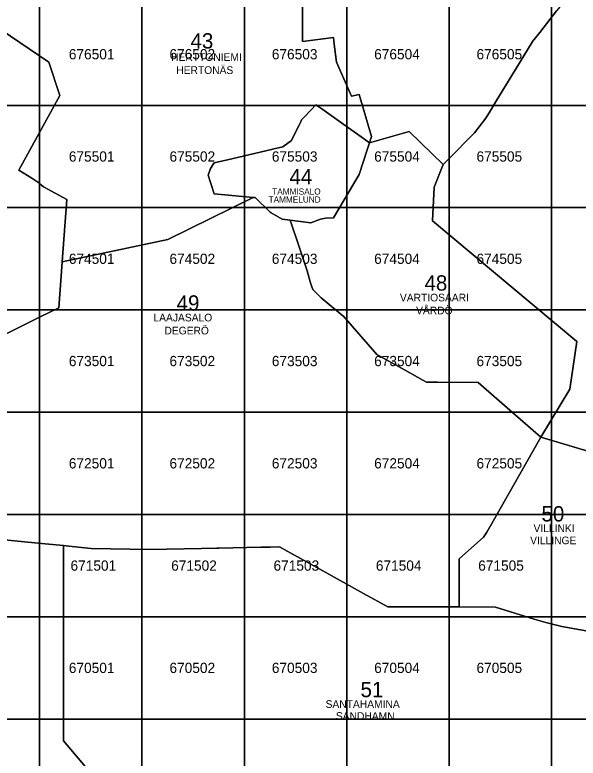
# Model space of a CAD drawing. Extents: x 25485000 to 25520000, y 6656775 to 6690000.
# Drawn here: x 25500758 to 25506262, y 6669617 to 6676885 of the extents above; entities that cross this region are included whole.
import ezdxf

# ---------------------------------------------------------------- set-up
doc = ezdxf.new("R2010")
doc.units = 0
doc.layers.add('Level 63', color=7, linetype='Continuous')

msp = doc.modelspace()

# ---------------------------------------------------------------- linework, layer by layer
at = {"layer": 'Level 63'}
for points in [[(25506321.3, 6677251.8), (25506203.7, 6677109.7), (25506049.4, 6676923.5), (25505887.3, 6676713.1), (25505815.7, 6676624.4), (25505811, 6676618.2), (25505576.6, 6676232), (25505550.7, 6676189.2), (25505535.7, 6676164.4), (25505465.4, 6676048), (25505444.7, 6676013.7), (25505402.6, 6675943.9), (25505360.4, 6675873.9), (25505248.6, 6675730.3), (25504991.1, 6675470.2), (25504941.6, 6675420.2), (25504854.1, 6675200.3), (25504837.4, 6674871.4), (25505612.3, 6674222.2), (25506247.7, 6673689.9), (25506181.2, 6673225), (25505895.6, 6672754.3), (25506849.3, 6672473)], [(25500427.3, 6676867.8), (25501089.3, 6676421.3), (25501195.8, 6676096.2), (25500795.1, 6675367.1), (25500923.2, 6675287.2), (25500990.4, 6675243.8), (25501002.9, 6675233.3), (25501038.4, 6675203.7), (25501266.2, 6675078.7), (25501221.4, 6674470.4), (25502253, 6674688.7), (25503087.4, 6675099.5), (25502704.3, 6675133.4), (25502675.4, 6675225.8), (25502669.1, 6675246), (25502647, 6675317.3), (25502668.1, 6675383.4), (25502704.6, 6675438.5), (25502834.9, 6675468.7), (25503264.5, 6675568.3), (25503274.3, 6675570.6), (25503376.8, 6675594.3), (25503462.2, 6675655.5), (25503527.3, 6675789.1), (25503538.6, 6675813.6), (25503547.9, 6675833.6), (25503560, 6675859.5), (25503593.1, 6675893.5), (25503640.2, 6675943.1), (25503649.2, 6675952.5), (25503698.8, 6676004.7), (25503757.2, 6675964.8), (25504165.1, 6675676.5), (25504222.9, 6675632.8), (25504242.8, 6675694.6), (25504121.7, 6676106.9), (25504046.4, 6676088.7), (25504020.2, 6676149), (25503902, 6676421.7), (25503879.2, 6676598.2), (25503872.4, 6676664.5), (25503567, 6676625), (25503567.2, 6677219.8)], [(25503567.2, 6677219.8), (25503567, 6676625), (25503872.4, 6676664.5), (25503879.2, 6676598.2), (25503902, 6676421.7), (25504020.2, 6676149), (25504046.4, 6676088.7), (25504121.7, 6676106.9), (25504242.8, 6675694.6), (25504222.9, 6675632.8), (25504609.9, 6675742.9), (25504941.6, 6675420.2), (25504991.1, 6675470.2), (25505248.6, 6675730.3), (25505360.4, 6675873.9), (25505402.6, 6675943.9), (25505444.7, 6676013.7), (25505465.4, 6676048), (25505535.7, 6676164.4), (25505550.7, 6676189.2), (25505576.6, 6676232), (25505811, 6676618.2), (25505815.7, 6676624.4), (25505887.3, 6676713.1), (25506049.4, 6676923.5)], [(25500113.5, 6673489.1), (25501011.9, 6673933.9), (25501087.9, 6673971.5), (25501188.3, 6674021.2), (25501217.7, 6674420.4), (25501221.4, 6674470.4), (25501266.2, 6675078.7), (25501038.4, 6675203.7), (25501002.9, 6675233.3), (25500990.4, 6675243.8), (25500923.2, 6675287.2), (25500795.1, 6675367.1), (25501195.8, 6676096.2), (25501089.3, 6676421.3), (25500427.3, 6676867.8)], [(25500288.5, 6671786.1), (25501016.8, 6671717.1), (25501234.3, 6671696.4), (25501284.3, 6671691.1), (25501501.9, 6671667.7), (25502074.6, 6671657.9), (25502581.3, 6671666.7), (25502732.6, 6671669.8), (25502749.6, 6671670.1), (25503162.4, 6671678.6), (25503251.4, 6671680.2), (25503342.3, 6671682), (25503424.7, 6671636.6), (25503737.3, 6671464.4), (25504165.7, 6671228.3), (25504402.1, 6671098), (25505098.3, 6671097.8), (25505098.9, 6671565.1), (25505338.2, 6671778.3), (25505368.1, 6671827.6), (25505430.9, 6671933.9), (25505895.6, 6672754.3), (25505619.5, 6672997.6), (25505286.3, 6673291.1), (25504886.4, 6673292.4), (25504778.4, 6673292.7), (25504743.5, 6673311.5), (25504563.9, 6673412.4), (25504293.6, 6673564.2), (25503965.3, 6673941.3), (25503961.8, 6673943.6), (25503771.6, 6674101.5), (25503750.8, 6674118.7), (25503734.5, 6674133.1), (25503728.5, 6674140.5), (25503669.5, 6674198.8), (25503655.6, 6674234.6), (25503641.9, 6674273.2), (25503614.6, 6674383.5), (25503535.2, 6674617.9), (25503447.4, 6674877.1), (25503368.7, 6674887.3), (25503263.4, 6674948.6), (25503252.9, 6674955), (25503105.8, 6675098.2), (25503087.4, 6675099.5), (25502253, 6674688.7), (25501221.4, 6674470.4), (25501217.7, 6674420.4), (25501188.3, 6674021.2), (25501087.9, 6673971.5), (25501011.9, 6673933.9), (25500113.5, 6673489.1)], [(25506354.9, 6670858.7), (25506103.8, 6670903), (25505947.4, 6670942.2), (25505831.7, 6670977.7), (25505453.8, 6671092.6), (25505098.3, 6671097.8), (25504402.1, 6671098), (25504165.7, 6671228.3), (25503737.3, 6671464.4), (25503424.7, 6671636.6), (25503342.3, 6671682), (25503251.4, 6671680.2), (25503162.4, 6671678.6), (25502749.6, 6671670.1), (25502732.6, 6671669.8), (25502581.3, 6671666.7), (25502074.6, 6671657.9), (25501501.9, 6671667.7), (25501284.3, 6671691.1), (25501234.3, 6671696.4), (25501232.7, 6670417.8), (25501232, 6669785), (25501556.1, 6669404.6)]]:
    msp.add_lwpolyline(points, dxfattribs=at)
for points in [[(25500000, 6676000), (25501000, 6676000), (25501000, 6677000), (25500000, 6677000)], [(25501000, 6676000), (25502000, 6676000), (25502000, 6677000), (25501000, 6677000)], [(25502000, 6676000), (25503000, 6676000), (25503000, 6677000), (25502000, 6677000)], [(25503000, 6676000), (25504000, 6676000), (25504000, 6677000), (25503000, 6677000)], [(25504000, 6676000), (25505000, 6676000), (25505000, 6677000), (25504000, 6677000)], [(25505000, 6676000), (25506000, 6676000), (25506000, 6677000), (25505000, 6677000)], [(25506000, 6676000), (25507000, 6676000), (25507000, 6677000), (25506000, 6677000)], [(25500000, 6675000), (25501000, 6675000), (25501000, 6676000), (25500000, 6676000)], [(25501000, 6675000), (25502000, 6675000), (25502000, 6676000), (25501000, 6676000)], [(25502000, 6675000), (25503000, 6675000), (25503000, 6676000), (25502000, 6676000)], [(25502675.4, 6675225.8), (25502704.3, 6675133.4), (25503087.4, 6675099.5), (25503105.8, 6675098.2), (25503252.9, 6674955), (25503263.4, 6674948.6), (25503368.7, 6674887.3), (25503447.4, 6674877.1), (25503648.9, 6674850.4), (25503744.9, 6674888.6), (25503793, 6674897.6), (25503870.2, 6674899.7), (25504121.9, 6675322.5), (25504201.6, 6675566.5), (25504222.9, 6675632.8), (25504165.1, 6675676.5), (25503757.2, 6675964.8), (25503698.8, 6676004.7), (25503649.2, 6675952.5), (25503640.2, 6675943.1), (25503593.1, 6675893.5), (25503560, 6675859.5), (25503547.9, 6675833.6), (25503538.6, 6675813.6), (25503527.3, 6675789.1), (25503462.2, 6675655.5), (25503376.8, 6675594.3), (25503274.3, 6675570.6), (25503264.5, 6675568.3), (25502834.9, 6675468.7), (25502704.6, 6675438.5), (25502668.1, 6675383.4), (25502647, 6675317.3), (25502669.1, 6675246)], [(25503000, 6675000), (25504000, 6675000), (25504000, 6676000), (25503000, 6676000)], [(25504000, 6675000), (25505000, 6675000), (25505000, 6676000), (25504000, 6676000)], [(25505000, 6675000), (25506000, 6675000), (25506000, 6676000), (25505000, 6676000)], [(25506000, 6675000), (25507000, 6675000), (25507000, 6676000), (25506000, 6676000)], [(25503447.4, 6674877.1), (25503535.2, 6674617.9), (25503614.6, 6674383.5), (25503641.9, 6674273.2), (25503655.6, 6674234.6), (25503669.5, 6674198.8), (25503728.5, 6674140.5), (25503734.5, 6674133.1), (25503750.8, 6674118.7), (25503771.6, 6674101.5), (25503961.8, 6673943.6), (25503965.3, 6673941.3), (25504293.6, 6673564.2), (25504563.9, 6673412.4), (25504743.5, 6673311.5), (25504778.4, 6673292.7), (25504886.4, 6673292.4), (25505286.3, 6673291.1), (25505619.5, 6672997.6), (25505895.6, 6672754.3), (25506181.2, 6673225), (25506247.7, 6673689.9), (25505612.3, 6674222.2), (25504837.4, 6674871.4), (25504854.1, 6675200.3), (25504941.6, 6675420.2), (25504609.9, 6675742.9), (25504222.9, 6675632.8), (25504201.6, 6675566.5), (25504121.9, 6675322.5), (25503870.2, 6674899.7), (25503793, 6674897.6), (25503744.9, 6674888.6), (25503648.9, 6674850.4)], [(25500000, 6674000), (25501000, 6674000), (25501000, 6675000), (25500000, 6675000)], [(25501000, 6674000), (25502000, 6674000), (25502000, 6675000), (25501000, 6675000)], [(25502000, 6674000), (25503000, 6674000), (25503000, 6675000), (25502000, 6675000)], [(25503000, 6674000), (25504000, 6674000), (25504000, 6675000), (25503000, 6675000)], [(25504000, 6674000), (25505000, 6674000), (25505000, 6675000), (25504000, 6675000)], [(25505000, 6674000), (25506000, 6674000), (25506000, 6675000), (25505000, 6675000)], [(25506000, 6674000), (25507000, 6674000), (25507000, 6675000), (25506000, 6675000)], [(25500000, 6673000), (25501000, 6673000), (25501000, 6674000), (25500000, 6674000)], [(25501000, 6673000), (25502000, 6673000), (25502000, 6674000), (25501000, 6674000)], [(25502000, 6673000), (25503000, 6673000), (25503000, 6674000), (25502000, 6674000)], [(25503000, 6673000), (25504000, 6673000), (25504000, 6674000), (25503000, 6674000)], [(25504000, 6673000), (25505000, 6673000), (25505000, 6674000), (25504000, 6674000)], [(25505000, 6673000), (25506000, 6673000), (25506000, 6674000), (25505000, 6674000)], [(25506000, 6673000), (25507000, 6673000), (25507000, 6674000), (25506000, 6674000)], [(25500000, 6672000), (25501000, 6672000), (25501000, 6673000), (25500000, 6673000)], [(25501000, 6672000), (25502000, 6672000), (25502000, 6673000), (25501000, 6673000)], [(25502000, 6672000), (25503000, 6672000), (25503000, 6673000), (25502000, 6673000)], [(25503000, 6672000), (25504000, 6672000), (25504000, 6673000), (25503000, 6673000)], [(25504000, 6672000), (25505000, 6672000), (25505000, 6673000), (25504000, 6673000)], [(25505000, 6672000), (25506000, 6672000), (25506000, 6673000), (25505000, 6673000)], [(25506000, 6672000), (25507000, 6672000), (25507000, 6673000), (25506000, 6673000)], [(25505098.3, 6671097.8), (25505453.8, 6671092.6), (25505831.7, 6670977.7), (25505947.4, 6670942.2), (25506103.8, 6670903), (25506354.9, 6670858.7), (25506885.4, 6670907.4), (25508230.7, 6671039.1), (25508934.1, 6671264.5), (25508847.6, 6671851), (25508747.3, 6672530.9), (25508115.8, 6672479.6), (25506981.5, 6672473.7), (25506849.3, 6672473), (25505895.6, 6672754.3), (25505430.9, 6671933.9), (25505368.1, 6671827.6), (25505338.2, 6671778.3), (25505098.9, 6671565.1)], [(25500000, 6671000), (25501000, 6671000), (25501000, 6672000), (25500000, 6672000)], [(25501000, 6671000), (25502000, 6671000), (25502000, 6672000), (25501000, 6672000)], [(25502000, 6671000), (25503000, 6671000), (25503000, 6672000), (25502000, 6672000)], [(25503000, 6671000), (25504000, 6671000), (25504000, 6672000), (25503000, 6672000)], [(25504000, 6671000), (25505000, 6671000), (25505000, 6672000), (25504000, 6672000)], [(25505000, 6671000), (25506000, 6671000), (25506000, 6672000), (25505000, 6672000)], [(25506000, 6671000), (25507000, 6671000), (25507000, 6672000), (25506000, 6672000)], [(25497356.9, 6670409.6), (25497406.6, 6670359.6), (25499970.4, 6667780), (25500575.9, 6667170.8), (25501637.6, 6667310.5), (25501556.1, 6669404.6), (25501232, 6669785), (25501232.7, 6670417.8), (25501234.3, 6671696.4), (25501016.8, 6671717.1), (25500288.5, 6671786.1), (25497878.5, 6670960.8), (25497621.7, 6671122), (25497571.8, 6671153.4), (25497411.6, 6670925.7)], [(25500000, 6670000), (25501000, 6670000), (25501000, 6671000), (25500000, 6671000)], [(25501000, 6670000), (25502000, 6670000), (25502000, 6671000), (25501000, 6671000)], [(25502000, 6670000), (25503000, 6670000), (25503000, 6671000), (25502000, 6671000)], [(25503000, 6670000), (25504000, 6670000), (25504000, 6671000), (25503000, 6671000)], [(25504000, 6670000), (25505000, 6670000), (25505000, 6671000), (25504000, 6671000)], [(25505000, 6670000), (25506000, 6670000), (25506000, 6671000), (25505000, 6671000)], [(25506000, 6670000), (25507000, 6670000), (25507000, 6671000), (25506000, 6671000)], [(25500000, 6669000), (25501000, 6669000), (25501000, 6670000), (25500000, 6670000)], [(25501000, 6669000), (25502000, 6669000), (25502000, 6670000), (25501000, 6670000)], [(25502000, 6669000), (25503000, 6669000), (25503000, 6670000), (25502000, 6670000)], [(25503000, 6669000), (25504000, 6669000), (25504000, 6670000), (25503000, 6670000)], [(25504000, 6669000), (25505000, 6669000), (25505000, 6670000), (25504000, 6670000)], [(25505000, 6669000), (25506000, 6669000), (25506000, 6670000), (25505000, 6670000)], [(25506000, 6669000), (25507000, 6669000), (25507000, 6670000), (25506000, 6670000)]]:
    msp.add_lwpolyline(points, close=True, dxfattribs=at)

# ---------------------------------------------------------------- texts
for s, height, p in [('43', 150, (25502474, 6676555.4)), ('676501', 100, (25501285.1, 6676450)), ('676502', 100, (25502268.5, 6676450)), ('676503', 100, (25503268.5, 6676450)), ('676504', 100, (25504268.5, 6676450)), ('676505', 100, (25505268.5, 6676450)), ('HERTTONIEMI', 75, (25502284.3, 6676434.4)), ('HERTONÄS', 75, (25502334.9, 6676306.9)), ('675501', 100, (25501285.1, 6675450)), ('675502', 100, (25502268.5, 6675450)), ('675503', 100, (25503268.5, 6675450)), ('675504', 100, (25504268.5, 6675450)), ('675505', 100, (25505268.5, 6675450)), ('44', 150, (25503440.4, 6675227)), ('TAMMISALO', 60, (25503273, 6675127.2)), ('TAMMELUND', 60, (25503237.5, 6675049.3)), ('674501', 100, (25501285.1, 6674450)), ('674502', 100, (25502268.5, 6674450)), ('674503', 100, (25503268.5, 6674450)), ('674504', 100, (25504268.5, 6674450)), ('674505', 100, (25505268.5, 6674450)), ('48', 150, (25504760, 6674188.5)), ('49', 150, (25502338.3, 6673992.5)), ('VARTIOSAARI', 75, (25504520.3, 6674083)), ('VÅRDÖ', 75, (25504677.9, 6673956.6)), ('LAAJASALO', 75, (25502112, 6673887.4)), ('DEGERÖ', 75, (25502219.2, 6673760.4)), ('673501', 100, (25501285.1, 6673450)), ('673502', 100, (25502268.5, 6673450)), ('673503', 100, (25503268.5, 6673450)), ('673504', 100, (25504268.5, 6673450)), ('673505', 100, (25505268.5, 6673450)), ('672501', 100, (25501285.1, 6672450)), ('672502', 100, (25502268.5, 6672450)), ('672503', 100, (25503268.5, 6672450)), ('672504', 100, (25504268.5, 6672450)), ('672505', 100, (25505268.5, 6672450)), ('50', 150, (25505903.3, 6671931.4)), ('VILLINKI', 75, (25505826, 6671826.9)), ('VILLINGE', 75, (25505792.8, 6671708.9)), ('671501', 100, (25501301.6, 6671450)), ('671502', 100, (25502285.1, 6671450)), ('671503', 100, (25503285.1, 6671450)), ('671504', 100, (25504285.1, 6671450)), ('671505', 100, (25505285.1, 6671450)), ('670501', 100, (25501285.1, 6670450)), ('670502', 100, (25502268.5, 6670450)), ('670503', 100, (25503268.5, 6670450)), ('670504', 100, (25504268.5, 6670450)), ('670505', 100, (25505268.5, 6670450)), ('51', 150, (25504135.3, 6670213.4)), ('SANTAHAMINA', 75, (25503793.9, 6670108.5)), ('SANDHAMN', 75, (25503894.2, 6669991.6))]:
    msp.add_text(s, height=height, dxfattribs=at).set_placement(p)

doc.saveas('drawing.dxf')
